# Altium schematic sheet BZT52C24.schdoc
size 127 x 101 mm
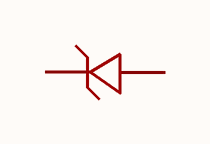
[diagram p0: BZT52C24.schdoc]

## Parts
D?  bzt52c24_c173422  [SOD-123_L2.7-W1.6-LS3.7-RD]  (value not drawn)

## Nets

Not connected (* = marked no-connect by the designer): D? 1(K) 2(A)

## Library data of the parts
D? = bzt52c24_c173422: 二极管配置:1个独立式;稳压值(标称值):24V;稳压值(范围):22.8V~25.2V;耗散功率(Pd):500mW;; Manufacturer: MDD(辰达半导体); AddInBom: yes; ModelId: ad7e39f9e5534b3c96ffdc5532ebb493; ModelName: SOD-123_L2.7-W1.6-H1.4-LS3.7; ModelTransform: 146.026,62.992,0,180,0,0,0.0005,0,0; Diode Configuration: 1个独立式; Zener Voltage(Nom): 24V; Reverse Leakage Current (Ir): 100nA@19V; Pd - Power Dissipation: 500mW; Impedance(Zzt): 60Ω; Tolerance: ±5%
